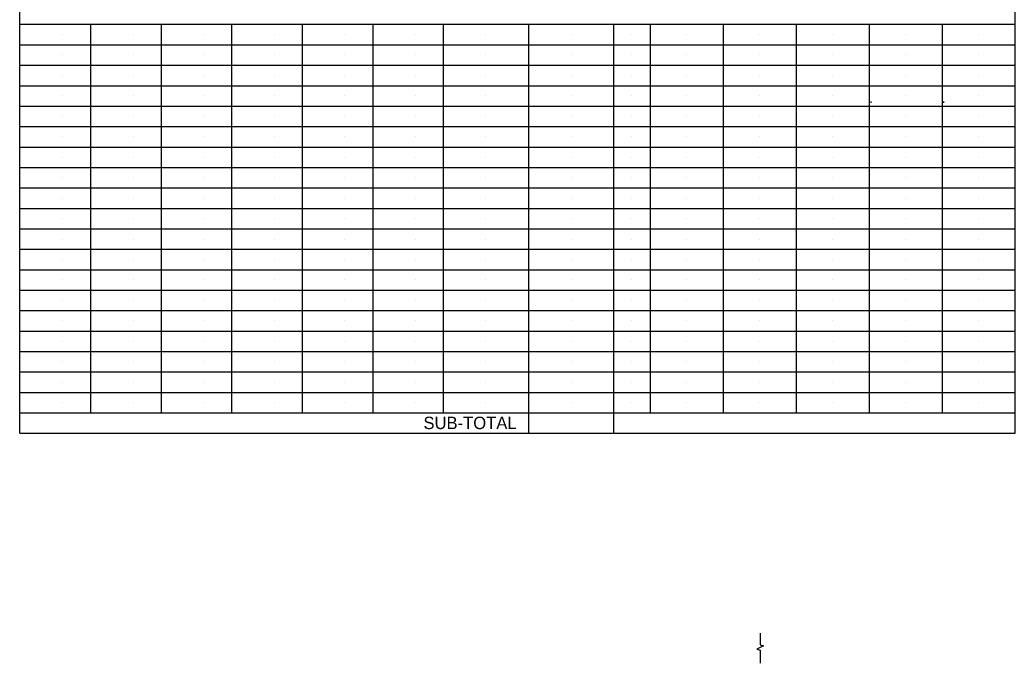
# Model space of a CAD drawing. Extents: x -16.6 to 33.3, y -8.6 to 39.2.
# Drawn here: x 17.16 to 30.79, y 22.61 to 31.42 of the extents above; entities that cross this region are included whole.
import ezdxf

# ---------------------------------------------------------------- set-up
doc = ezdxf.new("R2010")
doc.units = 0
doc.layers.add('BR_X_Beam_Centerline', color=7, linetype='Continuous')

msp = doc.modelspace()

# ---------------------------------------------------------------- linework, layer by layer
at = {"layer": 'BR_X_Beam_Centerline'}
for p, q in [((17.157, 25.759), (17.157, 39.183)), ((30.791, 25.759), (30.791, 39.183)), ((17.157, 31.359), (30.791, 31.359)), ((18.124, 31.359), (18.124, 26.039)), ((19.091, 31.359), (19.091, 26.039)), ((20.057, 31.359), (20.057, 26.039)), ((21.024, 31.359), (21.024, 26.039)), ((21.991, 31.359), (21.991, 26.039)), ((22.957, 31.359), (22.957, 26.039)), ((24.124, 31.359), (24.124, 25.759)), ((25.291, 31.359), (25.291, 25.759)), ((25.791, 31.359), (25.791, 26.039)), ((26.791, 31.359), (26.791, 26.039)), ((27.791, 31.359), (27.791, 26.039)), ((28.791, 31.359), (28.791, 26.039)), ((29.791, 31.359), (29.791, 26.039)), ((29.791, 31.359), (29.791, 26.039)), ((17.741, 31.219), (17.741, 31.219)), ((18.707, 31.219), (18.707, 31.219)), ((19.674, 31.219), (19.674, 31.219)), ((20.641, 31.219), (20.641, 31.219)), ((21.607, 31.219), (21.607, 31.219)), ((22.574, 31.219), (22.574, 31.219)), ((23.541, 31.219), (23.541, 31.219)), ((24.708, 31.219), (24.708, 31.219)), ((25.541, 31.219), (25.541, 31.219)), ((26.291, 31.219), (26.291, 31.219)), ((27.291, 31.219), (27.291, 31.219)), ((28.291, 31.219), (28.291, 31.219)), ((29.291, 31.219), (29.291, 31.219)), ((30.291, 31.219), (30.291, 31.219)), ((17.157, 31.079), (30.791, 31.079)), ((17.741, 30.939), (17.741, 30.939)), ((18.707, 30.939), (18.707, 30.939)), ((19.674, 30.939), (19.674, 30.939)), ((20.641, 30.939), (20.641, 30.939)), ((21.607, 30.939), (21.607, 30.939)), ((22.574, 30.939), (22.574, 30.939)), ((23.541, 30.939), (23.541, 30.939)), ((24.708, 30.939), (24.708, 30.939)), ((25.541, 30.939), (25.541, 30.939)), ((26.291, 30.939), (26.291, 30.939)), ((27.291, 30.939), (27.291, 30.939)), ((28.291, 30.939), (28.291, 30.939)), ((29.291, 30.939), (29.291, 30.939)), ((30.291, 30.939), (30.291, 30.939)), ((17.157, 30.799), (30.791, 30.799)), ((17.741, 30.659), (17.741, 30.659)), ((18.707, 30.659), (18.707, 30.659)), ((19.674, 30.659), (19.674, 30.659)), ((20.641, 30.659), (20.641, 30.659)), ((21.607, 30.659), (21.607, 30.659)), ((22.574, 30.659), (22.574, 30.659)), ((23.541, 30.659), (23.541, 30.659)), ((24.708, 30.659), (24.708, 30.659)), ((25.541, 30.659), (25.541, 30.659)), ((26.291, 30.659), (26.291, 30.659)), ((27.291, 30.659), (27.291, 30.659)), ((28.291, 30.659), (28.291, 30.659)), ((29.291, 30.659), (29.291, 30.659)), ((30.291, 30.659), (30.291, 30.659)), ((17.157, 30.519), (30.791, 30.519)), ((17.741, 30.379), (17.741, 30.379)), ((18.707, 30.379), (18.707, 30.379)), ((19.674, 30.379), (19.674, 30.379)), ((20.641, 30.379), (20.641, 30.379)), ((21.607, 30.379), (21.607, 30.379)), ((22.574, 30.379), (22.574, 30.379)), ((23.541, 30.379), (23.541, 30.379)), ((24.708, 30.379), (24.708, 30.379)), ((25.541, 30.379), (25.541, 30.379)), ((26.291, 30.379), (26.291, 30.379)), ((27.291, 30.379), (27.291, 30.379)), ((28.291, 30.379), (28.291, 30.379)), ((28.821, 30.286), (28.821, 30.303)), ((29.291, 30.379), (29.291, 30.379)), ((29.816, 30.286), (29.816, 30.303)), ((30.291, 30.379), (30.291, 30.379)), ((17.157, 30.239), (30.791, 30.239)), ((17.741, 30.099), (17.741, 30.099)), ((18.707, 30.099), (18.707, 30.099)), ((19.674, 30.099), (19.674, 30.099)), ((20.641, 30.099), (20.641, 30.099)), ((21.607, 30.099), (21.607, 30.099)), ((22.574, 30.099), (22.574, 30.099)), ((23.541, 30.099), (23.541, 30.099)), ((24.708, 30.099), (24.708, 30.099)), ((25.541, 30.099), (25.541, 30.099)), ((26.291, 30.099), (26.291, 30.099)), ((27.291, 30.099), (27.291, 30.099)), ((28.291, 30.099), (28.291, 30.099)), ((29.291, 30.099), (29.291, 30.099)), ((30.291, 30.099), (30.291, 30.099)), ((17.157, 29.959), (30.791, 29.959)), ((17.741, 29.819), (17.741, 29.819)), ((18.707, 29.819), (18.707, 29.819)), ((19.674, 29.819), (19.674, 29.819)), ((20.641, 29.819), (20.641, 29.819)), ((21.607, 29.819), (21.607, 29.819)), ((22.574, 29.819), (22.574, 29.819)), ((23.541, 29.819), (23.541, 29.819)), ((24.708, 29.819), (24.708, 29.819)), ((25.541, 29.819), (25.541, 29.819)), ((26.291, 29.819), (26.291, 29.819)), ((27.291, 29.819), (27.291, 29.819)), ((28.291, 29.819), (28.291, 29.819)), ((29.291, 29.819), (29.291, 29.819)), ((30.291, 29.819), (30.291, 29.819)), ((17.157, 29.679), (30.791, 29.679)), ((17.741, 29.539), (17.741, 29.539)), ((18.707, 29.539), (18.707, 29.539)), ((19.674, 29.539), (19.674, 29.539)), ((20.641, 29.539), (20.641, 29.539)), ((21.607, 29.539), (21.607, 29.539)), ((22.574, 29.539), (22.574, 29.539)), ((23.541, 29.539), (23.541, 29.539)), ((24.708, 29.539), (24.708, 29.539)), ((25.541, 29.539), (25.541, 29.539)), ((26.291, 29.539), (26.291, 29.539)), ((27.291, 29.539), (27.291, 29.539)), ((28.291, 29.539), (28.291, 29.539)), ((29.291, 29.539), (29.291, 29.539)), ((30.291, 29.539), (30.291, 29.539)), ((17.157, 29.399), (30.791, 29.399)), ((17.741, 29.259), (17.741, 29.259)), ((18.707, 29.259), (18.707, 29.259)), ((19.674, 29.259), (19.674, 29.259)), ((20.641, 29.259), (20.641, 29.259)), ((21.607, 29.259), (21.607, 29.259)), ((22.574, 29.259), (22.574, 29.259)), ((23.541, 29.259), (23.541, 29.259)), ((24.708, 29.259), (24.708, 29.259)), ((25.541, 29.259), (25.541, 29.259)), ((26.291, 29.259), (26.291, 29.259)), ((27.291, 29.259), (27.291, 29.259)), ((28.291, 29.259), (28.291, 29.259)), ((29.291, 29.259), (29.291, 29.259)), ((30.291, 29.259), (30.291, 29.259)), ((17.157, 29.119), (30.791, 29.119)), ((17.741, 28.979), (17.741, 28.979)), ((18.707, 28.979), (18.707, 28.979)), ((19.674, 28.979), (19.674, 28.979)), ((20.641, 28.979), (20.641, 28.979)), ((21.607, 28.979), (21.607, 28.979)), ((22.574, 28.979), (22.574, 28.979)), ((23.541, 28.979), (23.541, 28.979)), ((24.708, 28.979), (24.708, 28.979)), ((25.541, 28.979), (25.541, 28.979)), ((26.291, 28.979), (26.291, 28.979)), ((27.291, 28.979), (27.291, 28.979)), ((28.291, 28.979), (28.291, 28.979)), ((29.291, 28.979), (29.291, 28.979)), ((30.291, 28.979), (30.291, 28.979)), ((17.157, 28.839), (30.791, 28.839)), ((17.741, 28.699), (17.741, 28.699)), ((18.707, 28.699), (18.707, 28.699)), ((19.674, 28.699), (19.674, 28.699)), ((20.641, 28.699), (20.641, 28.699)), ((21.607, 28.699), (21.607, 28.699)), ((22.574, 28.699), (22.574, 28.699)), ((23.541, 28.699), (23.541, 28.699)), ((24.708, 28.699), (24.708, 28.699)), ((25.541, 28.699), (25.541, 28.699)), ((26.291, 28.699), (26.291, 28.699)), ((27.291, 28.699), (27.291, 28.699)), ((28.291, 28.699), (28.291, 28.699)), ((29.291, 28.699), (29.291, 28.699)), ((30.291, 28.699), (30.291, 28.699)), ((17.157, 28.559), (30.791, 28.559)), ((17.741, 28.419), (17.741, 28.419)), ((18.707, 28.419), (18.707, 28.419)), ((19.674, 28.419), (19.674, 28.419)), ((20.641, 28.419), (20.641, 28.419)), ((21.607, 28.419), (21.607, 28.419)), ((22.574, 28.419), (22.574, 28.419)), ((23.541, 28.419), (23.541, 28.419)), ((24.708, 28.419), (24.708, 28.419)), ((25.541, 28.419), (25.541, 28.419)), ((26.291, 28.419), (26.291, 28.419)), ((27.291, 28.419), (27.291, 28.419)), ((28.291, 28.419), (28.291, 28.419)), ((29.291, 28.419), (29.291, 28.419)), ((30.291, 28.419), (30.291, 28.419)), ((17.157, 28.279), (30.791, 28.279)), ((17.741, 28.139), (17.741, 28.139)), ((18.707, 28.139), (18.707, 28.139)), ((19.674, 28.139), (19.674, 28.139)), ((20.641, 28.139), (20.641, 28.139)), ((21.607, 28.139), (21.607, 28.139)), ((22.574, 28.139), (22.574, 28.139)), ((23.541, 28.139), (23.541, 28.139)), ((24.708, 28.139), (24.708, 28.139)), ((25.541, 28.139), (25.541, 28.139)), ((26.291, 28.139), (26.291, 28.139)), ((27.291, 28.139), (27.291, 28.139)), ((28.291, 28.139), (28.291, 28.139)), ((29.291, 28.139), (29.291, 28.139)), ((30.291, 28.139), (30.291, 28.139)), ((17.157, 27.999), (30.791, 27.999)), ((17.741, 27.859), (17.741, 27.859)), ((18.707, 27.859), (18.707, 27.859)), ((19.674, 27.859), (19.674, 27.859)), ((20.641, 27.859), (20.641, 27.859)), ((21.607, 27.859), (21.607, 27.859)), ((22.574, 27.859), (22.574, 27.859)), ((23.541, 27.859), (23.541, 27.859)), ((24.708, 27.859), (24.708, 27.859)), ((25.541, 27.859), (25.541, 27.859)), ((26.291, 27.859), (26.291, 27.859)), ((27.291, 27.859), (27.291, 27.859)), ((28.291, 27.859), (28.291, 27.859)), ((29.291, 27.859), (29.291, 27.859)), ((30.291, 27.859), (30.291, 27.859)), ((17.157, 27.719), (30.791, 27.719)), ((17.741, 27.579), (17.741, 27.579)), ((18.707, 27.579), (18.707, 27.579)), ((19.674, 27.579), (19.674, 27.579)), ((20.641, 27.579), (20.641, 27.579)), ((21.607, 27.579), (21.607, 27.579)), ((22.574, 27.579), (22.574, 27.579)), ((23.541, 27.579), (23.541, 27.579)), ((24.708, 27.579), (24.708, 27.579)), ((25.541, 27.579), (25.541, 27.579)), ((26.291, 27.579), (26.291, 27.579)), ((27.291, 27.579), (27.291, 27.579)), ((28.291, 27.579), (28.291, 27.579)), ((29.291, 27.579), (29.291, 27.579)), ((30.291, 27.579), (30.291, 27.579)), ((17.157, 27.439), (30.791, 27.439)), ((17.741, 27.299), (17.741, 27.299)), ((18.707, 27.299), (18.707, 27.299)), ((19.674, 27.299), (19.674, 27.299)), ((20.641, 27.299), (20.641, 27.299)), ((21.607, 27.299), (21.607, 27.299)), ((22.574, 27.299), (22.574, 27.299)), ((23.541, 27.299), (23.541, 27.299)), ((24.708, 27.299), (24.708, 27.299)), ((25.541, 27.299), (25.541, 27.299)), ((26.291, 27.299), (26.291, 27.299)), ((27.291, 27.299), (27.291, 27.299)), ((28.291, 27.299), (28.291, 27.299)), ((29.291, 27.299), (29.291, 27.299)), ((30.291, 27.299), (30.291, 27.299)), ((17.157, 27.159), (30.791, 27.159)), ((17.741, 27.019), (17.741, 27.019)), ((18.707, 27.019), (18.707, 27.019)), ((19.674, 27.019), (19.674, 27.019)), ((20.641, 27.019), (20.641, 27.019)), ((21.607, 27.019), (21.607, 27.019)), ((22.574, 27.019), (22.574, 27.019)), ((23.541, 27.019), (23.541, 27.019)), ((24.708, 27.019), (24.708, 27.019)), ((25.541, 27.019), (25.541, 27.019)), ((26.291, 27.019), (26.291, 27.019)), ((27.291, 27.019), (27.291, 27.019)), ((28.291, 27.019), (28.291, 27.019)), ((29.291, 27.019), (29.291, 27.019)), ((30.291, 27.019), (30.291, 27.019)), ((17.157, 26.879), (30.791, 26.879)), ((17.741, 26.739), (17.741, 26.739)), ((18.707, 26.739), (18.707, 26.739)), ((19.674, 26.739), (19.674, 26.739)), ((20.641, 26.739), (20.641, 26.739)), ((21.607, 26.739), (21.607, 26.739)), ((22.574, 26.739), (22.574, 26.739)), ((23.541, 26.739), (23.541, 26.739)), ((24.708, 26.739), (24.708, 26.739)), ((25.541, 26.739), (25.541, 26.739)), ((26.291, 26.739), (26.291, 26.739)), ((27.291, 26.739), (27.291, 26.739)), ((28.291, 26.739), (28.291, 26.739)), ((29.291, 26.739), (29.291, 26.739)), ((30.291, 26.739), (30.291, 26.739)), ((17.157, 26.599), (30.791, 26.599)), ((17.741, 26.459), (17.741, 26.459)), ((18.707, 26.459), (18.707, 26.459)), ((19.674, 26.459), (19.674, 26.459)), ((20.641, 26.459), (20.641, 26.459)), ((21.607, 26.459), (21.607, 26.459)), ((22.574, 26.459), (22.574, 26.459)), ((23.541, 26.459), (23.541, 26.459)), ((24.708, 26.459), (24.708, 26.459)), ((25.541, 26.459), (25.541, 26.459)), ((26.291, 26.459), (26.291, 26.459)), ((27.291, 26.459), (27.291, 26.459)), ((28.291, 26.459), (28.291, 26.459)), ((29.291, 26.459), (29.291, 26.459)), ((30.291, 26.459), (30.291, 26.459)), ((17.157, 26.319), (30.791, 26.319)), ((17.741, 26.179), (17.741, 26.179)), ((18.707, 26.179), (18.707, 26.179)), ((19.674, 26.179), (19.674, 26.179)), ((20.641, 26.179), (20.641, 26.179)), ((21.607, 26.179), (21.607, 26.179)), ((22.574, 26.179), (22.574, 26.179)), ((23.541, 26.179), (23.541, 26.179)), ((24.708, 26.179), (24.708, 26.179)), ((25.541, 26.179), (25.541, 26.179)), ((26.291, 26.179), (26.291, 26.179)), ((27.291, 26.179), (27.291, 26.179)), ((28.291, 26.179), (28.291, 26.179)), ((29.291, 26.179), (29.291, 26.179)), ((30.291, 26.179), (30.291, 26.179)), ((17.157, 26.039), (30.791, 26.039)), ((17.157, 25.759), (30.791, 25.759))]:
    msp.add_line(p, q, dxfattribs=at)
msp.add_lwpolyline([(27.3, 23.022), (27.3, 22.863), (27.345, 22.848), (27.255, 22.803), (27.3, 22.788), (27.3, 22.612)], dxfattribs=at)

# ---------------------------------------------------------------- texts
msp.add_text('SUB-TOTAL', height=0.17, dxfattribs=at).set_placement((22.686, 25.816))

doc.saveas('drawing.dxf')
